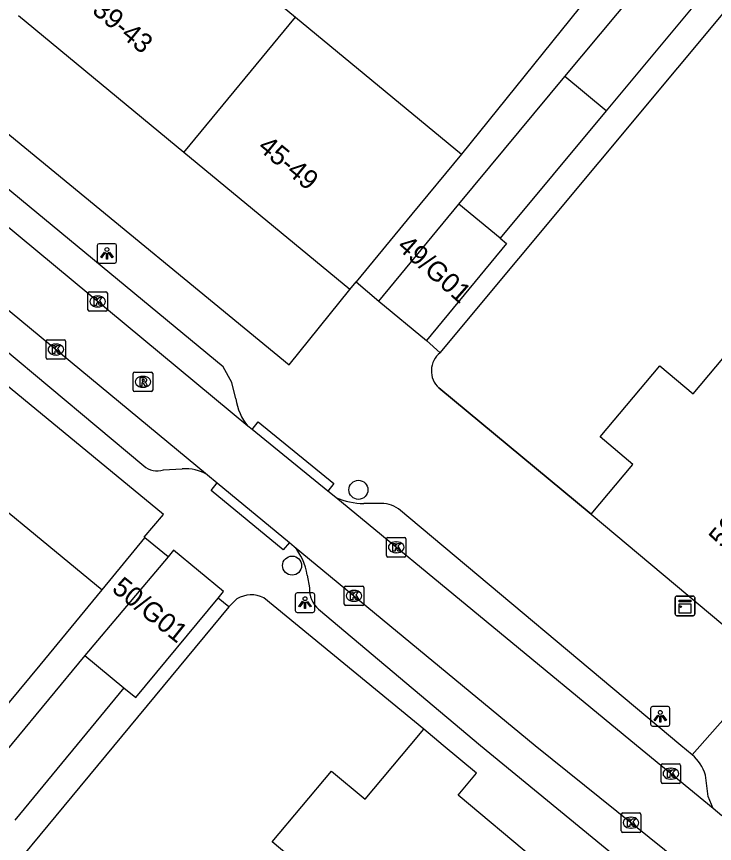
# Model space of a CAD drawing. Extents: x 162074 to 163034, y 381824 to 382557.
# Drawn here: x 162389.39 to 162425.19, y 381994.97 to 382037.39 of the extents above; entities that cross this region are included whole.
import ezdxf

# ---------------------------------------------------------------- set-up
doc = ezdxf.new("R2010")
doc.units = 0
for name, color, linetype in [('IMGEO_Boom', 7, 'Continuous'), ('IMGEO_Kast', 7, 'Continuous'), ('IMGEO_Kolk', 7, 'Continuous'), ('IMGEO_Lichtpunt', 7, 'Continuous'), ('IMGEO_Muur', 7, 'Continuous'), ('IMGEO_Pand', 7, 'Continuous'), ('IMGEO_Pand_nummerreeks', 7, 'Continuous'), ('IMGEO_Rijbaan_lokaal_open', 7, 'Continuous'), ('IMGEO_Rioolput', 7, 'Continuous'), ('IMGEO_Voetpad_open', 7, 'Continuous')]:
    doc.layers.add(name, color=color, linetype=linetype)

msp = doc.modelspace()

# ---------------------------------------------------------------- linework, layer by layer
at = {"layer": 'IMGEO_Boom'}
for centre in [(162406.926, 382013.109), (162403.524, 382009.222)]:
    msp.add_circle(centre, 0.489, dxfattribs=at)
at = {"layer": 'IMGEO_Kast'}
for p, q in [((162423.253, 382007.653), (162424.094, 382007.653)), ((162424.094, 382007.653), (162423.253, 382007.653)), ((162423.178, 382006.728), (162423.178, 382007.569)), ((162423.178, 382007.569), (162423.178, 382006.728)), ((162424.178, 382007.578), (162424.178, 382006.737)), ((162424.178, 382006.737), (162424.178, 382007.578)), ((162424.103, 382006.653), (162423.262, 382006.653)), ((162423.262, 382006.653), (162424.103, 382006.653))]:
    msp.add_line(p, q, dxfattribs=at)
for points in [[(162423.373, 382007.443), (162423.973, 382007.443), (162423.973, 382007.358), (162423.373, 382007.358), (162423.373, 382007.443)], [(162423.373, 382007.268), (162423.973, 382007.268), (162423.973, 382006.779), (162423.373, 382006.779), (162423.373, 382007.268)]]:
    msp.add_lwpolyline(points, dxfattribs=at)
msp.add_circle((162423.457, 382007.117), 0.0377, dxfattribs=at)
for centre, start, end in [((162423.256, 382007.575), 92.4484, 184.2845), ((162423.256, 382007.575), 92.4484, 184.2845), ((162424.1, 382007.575), 2.4484, 94.2845), ((162424.1, 382007.575), 2.4484, 94.2845), ((162423.256, 382006.731), 182.4484, 274.2845), ((162423.256, 382006.731), 182.4484, 274.2845), ((162424.1, 382006.731), 272.4484, 4.2845), ((162424.1, 382006.731), 272.4484, 4.2845)]:
    msp.add_arc(centre, 0.0779, start, end, dxfattribs=at)
at = {"layer": 'IMGEO_Kolk'}
for p, q in [((162393.049, 382022.347), (162393.049, 382023.199)), ((162393.124, 382023.273), (162393.976, 382023.273)), ((162393.537, 382023.053), (162393.562, 382023.053)), ((162394.05, 382023.199), (162394.05, 382022.347)), ((162393.56, 382022.493), (162393.535, 382022.493)), ((162393.976, 382022.273), (162393.124, 382022.273)), ((162390.981, 382020.807), (162391.833, 382020.807)), ((162390.906, 382019.881), (162390.906, 382020.733)), ((162391.394, 382020.587), (162391.419, 382020.587)), ((162391.907, 382020.733), (162391.907, 382019.881)), ((162391.417, 382020.027), (162391.392, 382020.027)), ((162391.833, 382019.807), (162390.981, 382019.807)), ((162408.438, 382010.662), (162409.29, 382010.662)), ((162408.363, 382009.736), (162408.363, 382010.588)), ((162408.851, 382010.442), (162408.876, 382010.442)), ((162409.364, 382010.588), (162409.364, 382009.736)), ((162408.874, 382009.882), (162408.849, 382009.882)), ((162409.29, 382009.662), (162408.438, 382009.662)), ((162406.201, 382007.244), (162406.201, 382008.096)), ((162406.276, 382008.17), (162407.128, 382008.17)), ((162407.202, 382008.096), (162407.202, 382007.244)), ((162406.689, 382007.95), (162406.714, 382007.95)), ((162406.712, 382007.39), (162406.687, 382007.39)), ((162407.128, 382007.17), (162406.276, 382007.17)), ((162422.454, 381998.122), (162422.454, 381998.974)), ((162422.529, 381999.048), (162423.381, 381999.048)), ((162422.942, 381998.828), (162422.967, 381998.828)), ((162423.455, 381998.974), (162423.455, 381998.122)), ((162423.381, 381998.048), (162422.529, 381998.048)), ((162422.965, 381998.268), (162422.94, 381998.268)), ((162420.411, 381995.605), (162420.411, 381996.457)), ((162420.486, 381996.531), (162421.338, 381996.531)), ((162420.899, 381996.311), (162420.924, 381996.311)), ((162421.412, 381996.457), (162421.412, 381995.605)), ((162420.922, 381995.751), (162420.897, 381995.751)), ((162421.338, 381995.531), (162420.486, 381995.531))]:
    msp.add_line(p, q, dxfattribs=at)
for points in [[(162393.049, 382022.347), (162393.049, 382023.199)], [(162393.124, 382023.273), (162393.976, 382023.273)], [(162393.37, 382022.973), (162393.493, 382022.973), (162393.493, 382022.822), (162393.623, 382022.973), (162393.787, 382022.973), (162393.641, 382022.822), (162393.794, 382022.573), (162393.642, 382022.573), (162393.557, 382022.737), (162393.493, 382022.67), (162393.493, 382022.573), (162393.37, 382022.573), (162393.37, 382022.973)], [(162394.05, 382023.199), (162394.05, 382022.347)], [(162393.976, 382022.273), (162393.124, 382022.273)], [(162390.981, 382020.807), (162391.833, 382020.807)], [(162390.906, 382019.881), (162390.906, 382020.733)], [(162391.227, 382020.507), (162391.35, 382020.507), (162391.35, 382020.356), (162391.48, 382020.507), (162391.644, 382020.507), (162391.498, 382020.356), (162391.651, 382020.107), (162391.499, 382020.107), (162391.414, 382020.271), (162391.35, 382020.204), (162391.35, 382020.107), (162391.227, 382020.107), (162391.227, 382020.507)], [(162391.907, 382020.733), (162391.907, 382019.881)], [(162391.833, 382019.807), (162390.981, 382019.807)], [(162408.438, 382010.662), (162409.29, 382010.662)], [(162408.363, 382009.736), (162408.363, 382010.588)], [(162408.684, 382010.362), (162408.807, 382010.362), (162408.807, 382010.211), (162408.937, 382010.362), (162409.101, 382010.362), (162408.955, 382010.211), (162409.108, 382009.962), (162408.956, 382009.962), (162408.871, 382010.126), (162408.807, 382010.059), (162408.807, 382009.962), (162408.684, 382009.962), (162408.684, 382010.362)], [(162409.364, 382010.588), (162409.364, 382009.736)], [(162409.29, 382009.662), (162408.438, 382009.662)], [(162406.201, 382007.244), (162406.201, 382008.096)], [(162406.276, 382008.17), (162407.128, 382008.17)], [(162407.202, 382008.096), (162407.202, 382007.244)], [(162406.522, 382007.87), (162406.645, 382007.87), (162406.645, 382007.719), (162406.775, 382007.87), (162406.939, 382007.87), (162406.793, 382007.719), (162406.946, 382007.47), (162406.794, 382007.47), (162406.709, 382007.634), (162406.645, 382007.567), (162406.645, 382007.47), (162406.522, 382007.47), (162406.522, 382007.87)], [(162407.128, 382007.17), (162406.276, 382007.17)], [(162422.454, 381998.122), (162422.454, 381998.974)], [(162422.529, 381999.048), (162423.381, 381999.048)], [(162422.775, 381998.748), (162422.898, 381998.748), (162422.898, 381998.597), (162423.028, 381998.748), (162423.192, 381998.748), (162423.046, 381998.597), (162423.199, 381998.348), (162423.047, 381998.348), (162422.962, 381998.512), (162422.898, 381998.445), (162422.898, 381998.348), (162422.775, 381998.348), (162422.775, 381998.748)], [(162423.455, 381998.974), (162423.455, 381998.122)], [(162423.381, 381998.048), (162422.529, 381998.048)], [(162420.411, 381995.605), (162420.411, 381996.457)], [(162420.486, 381996.531), (162421.338, 381996.531)], [(162420.732, 381996.231), (162420.855, 381996.231), (162420.855, 381996.08), (162420.985, 381996.231), (162421.149, 381996.231), (162421.003, 381996.08), (162421.156, 381995.831), (162421.004, 381995.831), (162420.919, 381995.995), (162420.855, 381995.928), (162420.855, 381995.831), (162420.732, 381995.831), (162420.732, 381996.231)], [(162421.412, 381996.457), (162421.412, 381995.605)], [(162421.338, 381995.531), (162420.486, 381995.531)]]:
    msp.add_lwpolyline(points, dxfattribs=at)
for centre, start, end in [((162393.126, 382023.197), 91.552, 178.448), ((162393.126, 382023.197), 91.552, 178.448), ((162393.974, 382023.197), 1.552, 88.448), ((162393.974, 382023.197), 1.552, 88.448), ((162393.126, 382022.349), 181.552, 268.448), ((162393.126, 382022.349), 181.552, 268.448), ((162393.974, 382022.349), 271.552, 358.448), ((162393.974, 382022.349), 271.552, 358.448), ((162390.983, 382020.731), 91.552, 178.448), ((162390.983, 382020.731), 91.552, 178.448), ((162391.831, 382020.731), 1.552, 88.448), ((162391.831, 382020.731), 1.552, 88.448), ((162390.983, 382019.883), 181.552, 268.448), ((162390.983, 382019.883), 181.552, 268.448), ((162391.831, 382019.883), 271.552, 358.448), ((162391.831, 382019.883), 271.552, 358.448), ((162408.44, 382010.586), 91.552, 178.448), ((162408.44, 382010.586), 91.552, 178.448), ((162409.288, 382010.586), 1.552, 88.448), ((162409.288, 382010.586), 1.552, 88.448), ((162408.44, 382009.738), 181.552, 268.448), ((162408.44, 382009.738), 181.552, 268.448), ((162409.288, 382009.738), 271.552, 358.448), ((162409.288, 382009.738), 271.552, 358.448), ((162406.278, 382008.094), 91.552, 178.448), ((162406.278, 382008.094), 91.552, 178.448), ((162407.126, 382008.094), 1.552, 88.448), ((162407.126, 382008.094), 1.552, 88.448), ((162406.278, 382007.246), 181.552, 268.448), ((162406.278, 382007.246), 181.552, 268.448), ((162407.126, 382007.246), 271.552, 358.448), ((162407.126, 382007.246), 271.552, 358.448), ((162422.531, 381998.972), 91.552, 178.448), ((162422.531, 381998.972), 91.552, 178.448), ((162423.379, 381998.972), 1.552, 88.448), ((162423.379, 381998.972), 1.552, 88.448), ((162422.531, 381998.124), 181.552, 268.448), ((162422.531, 381998.124), 181.552, 268.448), ((162423.379, 381998.124), 271.552, 358.448), ((162423.379, 381998.124), 271.552, 358.448), ((162420.488, 381996.455), 91.552, 178.448), ((162420.488, 381996.455), 91.552, 178.448), ((162421.336, 381996.455), 1.552, 88.448), ((162421.336, 381996.455), 1.552, 88.448), ((162420.488, 381995.607), 181.552, 268.448), ((162420.488, 381995.607), 181.552, 268.448), ((162421.336, 381995.607), 271.552, 358.448), ((162421.336, 381995.607), 271.552, 358.448)]:
    msp.add_arc(centre, 0.0765, start, end, dxfattribs=at)
for centre, major_axis, ratio, start_param, end_param in [((162393.536, 382022.773), (-0.387, 0.002), 0.722429, 4.712389, 7.853982), ((162393.561, 382022.773), (-0.39, 0.002), 0.717154, 1.570796, 4.712389), ((162391.393, 382020.307), (-0.387, 0.002), 0.722429, 4.712389, 7.853982), ((162391.418, 382020.307), (-0.39, 0.002), 0.717154, 1.570796, 4.712389), ((162408.85, 382010.162), (-0.387, 0.002), 0.722429, 4.712389, 7.853982), ((162408.875, 382010.162), (-0.39, 0.002), 0.717154, 1.570796, 4.712389), ((162406.688, 382007.67), (-0.387, 0.002), 0.722429, 4.712389, 7.853982), ((162406.713, 382007.67), (-0.39, 0.002), 0.717154, 1.570796, 4.712389), ((162422.941, 381998.548), (-0.387, 0.002), 0.722429, 4.712389, 7.853982), ((162422.966, 381998.548), (-0.39, 0.002), 0.717154, 1.570796, 4.712389), ((162420.898, 381996.031), (-0.387, 0.002), 0.722429, 4.712389, 7.853982), ((162420.923, 381996.031), (-0.39, 0.002), 0.717154, 1.570796, 4.712389)]:
    msp.add_ellipse(centre, major_axis=major_axis, ratio=ratio, start_param=start_param, end_param=end_param, dxfattribs=at)
at = {"layer": 'IMGEO_Lichtpunt'}
for p, q in [((162393.527, 382025.644), (162393.527, 382024.837)), ((162393.527, 382025.644), (162393.527, 382024.837)), ((162394.429, 382025.739), (162393.621, 382025.739)), ((162394.429, 382025.739), (162393.621, 382025.739)), ((162394.523, 382024.837), (162394.523, 382025.644)), ((162394.523, 382024.837), (162394.523, 382025.644)), ((162393.621, 382024.743), (162394.429, 382024.743)), ((162393.621, 382024.743), (162394.429, 382024.743)), ((162403.69, 382007.725), (162403.69, 382006.918)), ((162403.69, 382007.725), (162403.69, 382006.918)), ((162404.592, 382007.82), (162403.784, 382007.82)), ((162404.592, 382007.82), (162403.784, 382007.82)), ((162404.686, 382006.918), (162404.686, 382007.725)), ((162404.686, 382006.918), (162404.686, 382007.725)), ((162403.784, 382006.824), (162404.592, 382006.824)), ((162403.784, 382006.824), (162404.592, 382006.824)), ((162421.913, 382001.89), (162421.913, 382001.083)), ((162421.913, 382001.89), (162421.913, 382001.083)), ((162422.815, 382001.985), (162422.007, 382001.985)), ((162422.815, 382001.985), (162422.007, 382001.985)), ((162422.909, 382001.083), (162422.909, 382001.89)), ((162422.909, 382001.083), (162422.909, 382001.89)), ((162422.007, 382000.989), (162422.815, 382000.989)), ((162422.007, 382000.989), (162422.815, 382000.989))]:
    msp.add_line(p, q, dxfattribs=at)
for points in [[(162393.901, 382025.308), (162393.94, 382025.28), (162393.752, 382025.018), (162393.714, 382025.045), (162393.901, 382025.308)], [(162394.003, 382025.26), (162394.05, 382025.26), (162394.05, 382024.938), (162394.003, 382024.938), (162394.003, 382025.26)], [(162394.113, 382025.28), (162394.151, 382025.307), (162394.338, 382025.045), (162394.299, 382025.017), (162394.113, 382025.28)], [(162404.064, 382007.389), (162404.103, 382007.361), (162403.915, 382007.099), (162403.877, 382007.126), (162404.064, 382007.389)], [(162404.166, 382007.341), (162404.213, 382007.341), (162404.213, 382007.019), (162404.166, 382007.019), (162404.166, 382007.341)], [(162404.276, 382007.361), (162404.314, 382007.388), (162404.501, 382007.126), (162404.462, 382007.098), (162404.276, 382007.361)], [(162422.287, 382001.554), (162422.326, 382001.526), (162422.138, 382001.264), (162422.1, 382001.291), (162422.287, 382001.554)], [(162422.389, 382001.506), (162422.436, 382001.506), (162422.436, 382001.184), (162422.389, 382001.184), (162422.389, 382001.506)], [(162422.499, 382001.526), (162422.537, 382001.553), (162422.724, 382001.291), (162422.685, 382001.263), (162422.499, 382001.526)]]:
    msp.add_lwpolyline(points, dxfattribs=at)
for centre in [(162394.026, 382025.442), (162404.189, 382007.523), (162422.412, 382001.688)]:
    msp.add_circle(centre, 0.0994, dxfattribs=at)
for centre, start, end in [((162393.621, 382025.644), 90, 180), ((162393.621, 382025.644), 90, 180), ((162394.429, 382025.644), 0, 90), ((162394.429, 382025.644), 0, 90), ((162393.621, 382024.837), 180, 270), ((162393.621, 382024.837), 180, 270), ((162394.429, 382024.837), 270, 0), ((162394.429, 382024.837), 270, 360), ((162403.784, 382007.725), 90, 180), ((162403.784, 382007.725), 90, 180), ((162404.592, 382007.725), 0, 90), ((162404.592, 382007.725), 0, 90), ((162403.784, 382006.918), 180, 270), ((162403.784, 382006.918), 180, 270), ((162404.592, 382006.918), 270, 0), ((162404.592, 382006.918), 270, 360), ((162422.007, 382001.89), 90, 180), ((162422.007, 382001.89), 90, 180), ((162422.815, 382001.89), 0, 90), ((162422.815, 382001.89), 0, 90), ((162422.007, 382001.083), 180, 270), ((162422.007, 382001.083), 180, 270), ((162422.815, 382001.083), 270, 0), ((162422.815, 382001.083), 270, 360)]:
    msp.add_arc(centre, 0.0946, start, end, dxfattribs=at)
at = {"layer": 'IMGEO_Muur'}
for points in [[(162418.871, 382011.858), (162411.056, 382018.337)], [(162400.692, 382007.517), (162400.283, 382007.107)], [(162410.285, 382000.837), (162402.081, 382007.571)]]:
    msp.add_lwpolyline(points, dxfattribs=at)
for centre, radius, start, end in [((162411.854, 382019.214), 1.186, 128.1776, 227.7068), ((162401.437, 382006.253), 1.467, 63.9423, 120.5105)]:
    msp.add_arc(centre, radius, start, end, dxfattribs=at)
at = {"layer": 'IMGEO_Pand'}
for points in [[(162395.214, 382044.365), (162403.697, 382037.363)], [(162417.517, 382034.312), (162422.917, 382040.802)], [(162425.028, 382039.045), (162419.629, 382032.555)], [(162397.967, 382030.421), (162389.484, 382037.423)], [(162397.967, 382030.421), (162403.697, 382037.363)], [(162403.697, 382037.363), (162412.215, 382030.331)], [(162412.076, 382027.772), (162417.517, 382034.312)], [(162419.629, 382032.555), (162417.517, 382034.312)], [(162419.629, 382032.555), (162414.195, 382026.023)], [(162406.485, 382023.389), (162397.967, 382030.421)], [(162412.215, 382030.331), (162409.668, 382027.246), (162406.809, 382023.782)], [(162407.966, 382022.794), (162412.076, 382027.772)], [(162414.195, 382026.023), (162412.076, 382027.772)], [(162414.195, 382026.023), (162414.521, 382025.754), (162410.411, 382020.776)], [(162406.485, 382023.389), (162406.809, 382023.782)], [(162407.966, 382022.794), (162410.411, 382020.776)], [(162418.871, 382011.858), (162421.01, 382014.407), (162419.325, 382015.822), (162422.385, 382019.469), (162424.102, 382018.029), (162426.069, 382020.373)], [(162385.263, 382014.985), (162393.775, 382007.979)], [(162418.871, 382011.858), (162425.617, 382006.198)], [(162399.729, 382007.556), (162400.008, 382007.893), (162397.449, 382010.007), (162397.162, 382009.667)], [(162397.162, 382009.667), (162392.894, 382004.61)], [(162387.927, 382000.91), (162390.598, 382004.119), (162393.775, 382007.979)], [(162394.9, 382002.952), (162395.51, 382002.449), (162399.729, 382007.556)], [(162392.894, 382004.61), (162387.286, 381997.838)], [(162392.894, 382004.61), (162394.9, 382002.952)], [(162394.9, 382002.952), (162389.294, 381996.165)], [(162402.11, 381991.101), (162404.211, 381993.604), (162402.498, 381995.043), (162405.552, 381998.682), (162407.267, 381997.241), (162409.583, 382000), (162410.285, 382000.837)], [(162415.951, 381994.16), (162412.036, 381997.447), (162412.981, 381998.573), (162411.282, 382000), (162410.285, 382000.837)]]:
    msp.add_lwpolyline(points, dxfattribs=at)
at = {"layer": 'IMGEO_Rijbaan_lokaal_open'}
for points in [[(162401.258, 382016.375), (162376.073, 382037.278)], [(162382.599, 382027.589), (162399.187, 382013.878)], [(162401.469, 382016.204), (162401.258, 382016.375)], [(162405.36, 382013.046), (162401.469, 382016.204)], [(162399.187, 382013.878), (162399.687, 382013.465)], [(162399.687, 382013.465), (162403.386, 382010.41)], [(162405.772, 382012.711), (162405.36, 382013.046)], [(162425.125, 381996.757), (162421.191, 382000), (162405.772, 382012.711)], [(162403.386, 382010.41), (162403.637, 382010.203)], [(162403.637, 382010.203), (162415.991, 382000), (162423.494, 381993.957)], [(162425.57, 381996.39), (162425.125, 381996.757)]]:
    msp.add_lwpolyline(points, dxfattribs=at)
at = {"layer": 'IMGEO_Rioolput'}
for p, q in [((162395.449, 382019.153), (162396.301, 382019.153)), ((162395.374, 382018.227), (162395.374, 382019.079)), ((162395.862, 382018.933), (162395.887, 382018.933)), ((162396.375, 382019.079), (162396.375, 382018.227)), ((162395.885, 382018.373), (162395.86, 382018.373)), ((162396.301, 382018.153), (162395.449, 382018.153))]:
    msp.add_line(p, q, dxfattribs=at)
for points in [[(162395.449, 382019.153), (162396.301, 382019.153)], [(162395.374, 382018.227), (162395.374, 382019.079)], [(162395.963, 382018.851), (162395.711, 382018.853), (162395.711, 382018.453)], [(162395.889, 382018.772), (162395.835, 382018.772), (162395.835, 382018.691)], [(162395.835, 382018.691), (162395.887, 382018.691)], [(162396.375, 382019.079), (162396.375, 382018.227)], [(162395.711, 382018.453), (162395.835, 382018.453), (162395.835, 382018.615), (162395.846, 382018.615)], [(162395.893, 382018.586), (162395.964, 382018.453), (162396.104, 382018.453), (162396.039, 382018.579)], [(162396.301, 382018.153), (162395.449, 382018.153)]]:
    msp.add_lwpolyline(points, dxfattribs=at)
for centre, radius, start, end in [((162395.451, 382019.077), 0.0765, 91.552, 178.448), ((162395.451, 382019.077), 0.0765, 91.552, 178.448), ((162396.299, 382019.077), 0.0765, 1.552, 88.448), ((162396.299, 382019.077), 0.0765, 1.552, 88.448), ((162395.871, 382018.88), 0.19, 274.7715, 282.9687), ((162395.895, 382018.676), 0.0964, 77.0061, 93.1865), ((162395.909, 382018.733), 0.0378, 276.6634, 79.6772), ((162395.962, 382018.741), 0.109, 350.3612, 89.416), ((162395.96, 382018.741), 0.112, 277.5842, 350.9817), ((162395.845, 382018.562), 0.0533, 26.0293, 88.6989), ((162395.944, 382018.526), 0.108, 29.5134, 73.7905), ((162395.451, 382018.229), 0.0765, 181.552, 268.448), ((162395.451, 382018.229), 0.0765, 181.552, 268.448), ((162396.299, 382018.229), 0.0765, 271.552, 358.448), ((162396.299, 382018.229), 0.0765, 271.552, 358.448)]:
    msp.add_arc(centre, radius, start, end, dxfattribs=at)
for centre, major_axis, ratio, start_param, end_param in [((162395.861, 382018.653), (-0.387, 0.002), 0.722429, 4.712389, 7.853982), ((162395.886, 382018.653), (-0.39, 0.002), 0.717154, 1.570796, 4.712389)]:
    msp.add_ellipse(centre, major_axis=major_axis, ratio=ratio, start_param=start_param, end_param=end_param, dxfattribs=at)
at = {"layer": 'IMGEO_Voetpad_open'}
for points in [[(162344.316, 382086.382), (162352.681, 382096.404), (162420.1, 382040.13), (162412.215, 382030.331)], [(162335.334, 382075.475), (162336.332, 382074.657), (162403.368, 382019.529), (162406.485, 382023.389)], [(162395.976, 382010.646), (162395.928, 382010.685), (162396.934, 382011.836), (162328.967, 382067.842), (162327.721, 382066.46)], [(162411.121, 382020.146), (162431.473, 382044.558)], [(162400.637, 382017.775), (162400.437, 382018.613), (162399.995, 382019.427), (162379.183, 382036.614)], [(162383.84, 382024.438), (162395.917, 382014.336)], [(162406.809, 382023.782), (162407.966, 382022.794)], [(162410.411, 382020.776), (162411.121, 382020.146)], [(162411.056, 382018.337), (162418.871, 382011.858)], [(162401.469, 382016.204), (162401.782, 382016.593), (162405.673, 382013.435), (162405.36, 382013.046)], [(162396.919, 382014.13), (162397.884, 382014.19)], [(162403.386, 382010.41), (162403.069, 382010.024), (162399.37, 382013.079), (162399.687, 382013.465)], [(162407.969, 382012.408), (162407.208, 382012.411)], [(162424.051, 381999.518), (162423.467, 382000), (162408.984, 382012.139)], [(162393.775, 382007.979), (162395.976, 382010.646)], [(162397.162, 382009.667), (162395.976, 382010.646)], [(162404.302, 382008.738), (162404.414, 382008.077)], [(162400.283, 382007.107), (162399.729, 382007.556)], [(162400.692, 382007.517), (162400.283, 382007.107)], [(162410.285, 382000.837), (162402.081, 382007.571)], [(162400.283, 382007.107), (162379.962, 381982.583)], [(162404.88, 382006.984), (162413.186, 382000), (162420.062, 381994.354)], [(162428.079, 382004.082), (162424.051, 381999.518)], [(162425.125, 381996.757), (162424.875, 381997.372), (162424.723, 381998.477)]]:
    msp.add_lwpolyline(points, dxfattribs=at)
for centre, radius, start, end in [((162411.854, 382019.214), 1.186, 128.1776, 227.7068), ((162403.469, 382018.193), 2.863, 188.4046, 219.4368), ((162396.607, 382015.15), 1.067, 229.7321, 287.0329), ((162398.024, 382011.896), 2.298, 59.5867, 93.4817), ((162407.221, 382016.058), 3.647, 246.597, 269.8027), ((162408.068, 382010.734), 1.677, 56.9153, 93.3976), ((162401.381, 382008.296), 2.954, 8.6117, 40.2172), ((162405.778, 382008.013), 1.366, 177.309, 228.8729), ((162401.437, 382006.253), 1.467, 63.9423, 120.5105), ((162422.572, 381997.826), 2.247, 16.8393, 48.8479)]:
    msp.add_arc(centre, radius, start, end, dxfattribs=at)

# ---------------------------------------------------------------- texts
at = {"layer": 'IMGEO_Pand_nummerreeks'}
for s, rotation, p in [('39-43', 320.4601, (162393.212, 382037.613)), ('45-49', 320.4601, (162401.71, 382030.598)), ('49/G01', 318.6496, (162408.856, 382025.519)), ('56-60', 50.0153, (162425.579, 382010.081)), ('50/G01', 321.3425, (162394.223, 382007.942))]:
    msp.add_text(s, height=1, rotation=rotation, dxfattribs=at).set_placement(p)

doc.saveas('drawing.dxf')
